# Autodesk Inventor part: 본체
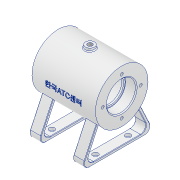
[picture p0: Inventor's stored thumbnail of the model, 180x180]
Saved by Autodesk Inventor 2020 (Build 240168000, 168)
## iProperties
Created: 2021-12
Part Number: 본체
Material: 알루미늄 6061
Document SubType Name: Modeling
Designer: MIRAE
Density: 2.7 g/cm^3
Appearance: 알루미늄 - 평지
Mass: 311.524 g
Surface Area: 356.187 cm^2
Volume: 115.379 cm^3
Author: MIRAE
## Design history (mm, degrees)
sketch "스케치2"
  geometry: L1 (-35, 0)-(35, 0); L2 (-35, 0)-(-35, 29); L3 (-35, 29)-(35, 29); L4 (35, 29)-(35, 0); 1 further point
  constraints: 8 end point, 2 perpendicular, 1 horizontal, 1 midpoint, 1 vertical
  dimensions: "d7" = 70 distance of L1.start L1.end; "d8" = 35 distance of point (0, 0) L1.start; "d9" = 58 diameter of L3 L1
revolve "회전1" sketch "스케치2" stored, may be unused: angle "d10" = 90 deg
sketch "스케치1"
  geometry: L1 (-35, 0)-(35, 0); L2 (-35, 0)-(-35, 16); L3 (-35, 16)-(-23, 16); L4 (-23, 16)-(-23, 14); L5 (-23, 14)-(-21, 14); L6 (-21, 14)-(-21, 21); L7 (-21, 21)-(21, 21); L8 (21, 21)-(21, 14); L9 (21, 14)-(23, 14); L10 (23, 14)-(23, 16); L11 (23, 16)-(35, 16); L12 (35, 16)-(35, 0); 1 further point
  constraints: 24 end point, 8 perpendicular, 4 point on line, 2 collinear, 1 horizontal, 1 midpoint, 1 vertical
  dimensions: "d0" = 70 distance of L1.start L1.end; "d1" = 35 distance of point (0, 0) L1.start; "d2" = 32 diameter of L3 L1; "d3" = 28 diameter of L5 L1; "d4" = 42 diameter of L7 L1; "d5" = 12 distance of L2.end L3.end; "d6" = 42 distance of L6.end L7.end
revolve "회전2" sketch "스케치1" stored, may be unused: angle "d11" = 90 deg
sketch "스케치5"
  geometry: C1 r 21 at (0, 0); 3 further points
  constraints: 2 vertical alignment, 1 centre point, 1 coincident, 1 other
  dimensions: "d20" = 42 diameter of C1
hole "구멍1" sketch "스케치5" at (0, 21) diameter "d21" = 3.242; stored, may be unused: countersink angle "d25" = 90 deg, drill point angle "d27" = 118 deg; dims "d22" = 8, "d23" = 4, "d24" = 2, "d26" = 10
sketch "스케치6"
  geometry: L1 (0, 0)-(-30.07, -10.945); L2 (0, 0)-(-29, 0); C1 r 1.621 at (0, 21) reference; C2 r 1.621 at (-21, 0) reference; C3 r 1.621 at (0, -21) reference; C4 r 1.621 at (21, 0) reference; C5 r 16 at (0, 0) reference; 1 further point
  constraints: 4 end point, 1 horizontal, 1 horizontal alignment, 1 other
  dimensions: "d31" = 32 distance of L1.start L1.end; "d32" = 20 deg angle of L1 L2
  node "투영된 루프4"
node "작업 평면3"
sketch "스케치7"
  geometry: C1 r 6 at (0, 0); 1 further point
  constraints: 1 centre point, 1 coincident
  dimensions: "d33" = 12 diameter of C1
extrude "돌출1" join sketch "스케치7" stored distance "d34" = 10; taper "d35" = 0 deg
sketch "스케치8"
  geometry: C1 r 6 at (0, 0) reference; 2 further points
  constraints: 1 coincident
hole "구멍2" sketch "스케치8" at (0, 0) diameter "d36" = 5.1881; stored, may be unused: countersink angle "d40" = 90 deg, drill point angle "d42" = 0 deg; dims "d37" = 12, "d38" = 4, "d39" = 2, "d41" = 19.5
node "작업 평면4"
sketch "스케치9"
  geometry: L1 (-35, -29)-(-35, 29) reference; L2 (35, -29)-(35, 29) reference; 3 further points
  constraints: 2 other
  dimensions: "d43" = 29 vertical distance of L1.end point (0, 0); "d44" = 35 horizontal distance of L1.end point (0, 0)
feature "엠보싱1" sketch "스케치9" dims "d0" = 70, "d1" = 35, "d2" = 32, "d3" = 28, "d4" = 42, "d5" = 12, "d6" = 42, "d45" = 0.5, "d46" = 0
node "작업 평면5"
sketch "스케치10"
  geometry: C1 r 5 at (0, 0); 1 further point
  constraints: 1 centre point, 1 coincident
  dimensions: "d48" = 10 diameter of C1
extrude "돌출2" join sketch "스케치10" stored distance "d49" = 10; taper "d50" = 0 deg
sketch "스케치11"
  geometry: C1 r 5 at (0, 0) reference; 2 further points
  constraints: 1 coincident
hole "구멍3" sketch "스케치11" at (0, 0) diameter "d51" = 5.1881; stored, may be unused: countersink angle "d55" = 90 deg, drill point angle "d57" = 118 deg; dims "d52" = 6, "d53" = 4, "d54" = 2, "d56" = 8
node "작업 평면6"
sketch "스케치12"
  geometry: 1 further point
hole "구멍4" sketch "스케치12" at (0, 0) diameter "d59" = 3; stored, may be unused: countersink angle "d63" = 90 deg, drill point angle "d65" = 0 deg; dims "d60" = 6, "d61" = 4, "d62" = 2, "d64" = 8
node "작업 평면7"
node "작업 평면9"
sketch "스케치16"
  geometry: L1 (-55, 40)-(-55, -40); L2 (-55, 40)-(-17.993, 22.743); L3 (-55, -40)-(-17.993, -22.743); C1 r 1.621 at (0, 21) reference; C2 r 1.621 at (-21, 0) reference; C3 r 1.621 at (0, -21) reference; C4 r 1.621 at (21, 0) reference; C5 r 16 at (0, 0) reference; C6 r 29 at (0, 0) reference; A1 r 29 centre (0, 0) between (-17.993, 22.743) and (-17.993, -22.743) reference; 4 further points
  constraints: 6 end point, 2 point on circle, 1 horizontal alignment, 1 midpoint, 1 vertical
  dimensions: "d83" = 80 distance of L1.start L1.end; "d84" = 55 distance from line of point (0, 0) L1; "d85" = 65 deg angle of L2 L1; "d86" = 65 deg angle of L1 L3
extrude "돌출4" join sketch "스케치16" distance "d87" = 12; taper "d88" = 0 deg
fillet "모깎기1" dims "d89" = 6
sketch "스케치17"
  geometry: L1 (36.02, -46.464)-(22.743, -17.993) reference; L2 (-22.743, -17.993)-(-36.02, -46.464) reference; L3 (-30.582, -55)-(30.582, -55) reference; L4 (-25.873, -52)-(25.873, -52); L5 (-20.574, -20.438)-(-31.311, -43.464); L6 (-22.743, -17.993)-(-36.02, -46.464) reference; L7 (31.311, -43.464)-(20.574, -20.438); L8 (36.02, -46.464)-(22.743, -17.993) reference; C1 r 1.621 at (-21, 0) reference; C2 r 1.621 at (0, -21) reference; C3 r 1.621 at (21, 0) reference; C4 r 1.621 at (0, 21) reference; C5 r 16 at (0, 0) reference; C6 r 29 at (0, 0) reference; A1 r 6 centre (30.582, -49) between (30.582, -55) and (36.02, -46.464) reference; A2 r 29 centre (0, 0) between (-22.743, -17.993) and (22.743, -17.993) reference; A3 r 6 centre (-30.582, -49) between (-36.02, -46.464) and (-30.582, -55) reference; A4 r 29 centre (0, 0) between (22.743, -17.993) and (-22.743, -17.993) reference; A5 r 6 centre (-25.873, -46) between (-31.311, -43.464) and (-25.873, -52); A6 r 6 centre (25.873, -46) between (25.873, -52) and (31.311, -43.464); 3 further points
  constraints: 6 end point, 6 point on circle, 4 tangent, 2 centre point, 2 parallel, 1 equal radius, 1 horizontal
  dimensions: "d90" = 3 distance between parallel lines of L4 L3; "d91" = 3 distance between parallel lines of L2 L5; "d92" = 3 distance between parallel lines of L1 L7; "d93" = 6 radius of A5
extrude "돌출5" cut sketch "스케치17" extent not by distance; stored distance "d94" = 0; taper "d95" = 0 deg
sketch "스케치18"
  geometry: L1 (-6, 43.873)-(42, 43.873); L2 (42, 43.873)-(42, 7.873); L3 (42, 7.873)-(-6, 7.873); L4 (-6, 7.873)-(-6, 43.873); L5 (-12, -4.709)-(-12, 56.455) reference; 2 further points
  constraints: 8 end point, 2 parallel, 1 horizontal, 1 horizontal alignment, 1 midpoint, 1 perpendicular
  dimensions: "d96" = 48 distance of L2.end L3.end; "d97" = 36 distance of L1.end L2.end; "d98" = 6 distance between parallel lines of L5 L4
hole "구멍5" sketch "스케치18" at (-6, 43.873), (42, 43.873), (42, 7.873), (-6, 7.873) diameter "d99" = 6; stored, may be unused: countersink angle "d103" = 90 deg, drill point angle "d105" = 0 deg; dims "d100" = 6, "d101" = 4, "d102" = 2, "d104" = 8
fillet "모깎기2" dims "d106" = 0.5
fillet "모깎기3" dims "d107" = 1
fillet "모깎기4" dims "d108" = 0.3
fillet "모깎기5" dims "d109" = 3
chamfer "모따기1" distance "d110" = 1; stored, may be unused: second distance "d111" = 2, angle "d112" = 45 deg
chamfer "모따기2" distance "d113" = 1; stored, may be unused: second distance "d114" = 2, angle "d115" = 45 deg
node "솔리드1"
pattern_circular "원형 패턴1" dims angle "d29" = 360 deg
mirror "미러1"
mirror "미러2"
node "투영된 루프5"
node "투영된 루프7"
node "투영된 루프8"
node "투영된 루프9"
feature "A9D066F2-1C7D-4E18-AEED-F7BC21143FA4" dims "d59" = 3, "d60" = 6, "d61" = 4, "d62" = 2, "d63" = 90 deg, "d64" = 8, "d65" = 0
other parameters: "d47" = 32, "d58" = 21, "d66" = -55
